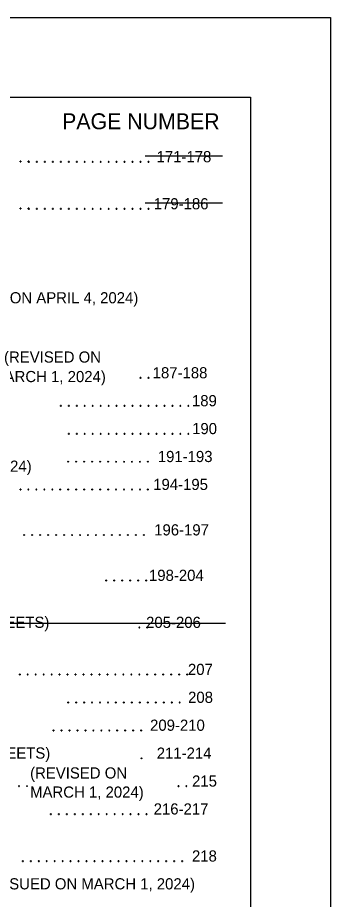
# Model space of a CAD drawing. Extents: x 0 to 1.42, y 0 to 0.92.
# Drawn here: x 1.2532 to 1.4167, y 0.4557 to 0.9167 of the extents above; entities that cross this region are included whole.
import ezdxf

# ---------------------------------------------------------------- set-up
doc = ezdxf.new("R2010")
doc.units = 0
for name, color, linetype in [('DRAFT_Text-Notes', 7, 'Continuous'), ('DRAFT_Text-Titles', 7, 'Continuous'), ('SHEET_Lines', 7, 'Continuous'), ('SHEET_Plot Boundary', 7, 'Continuous')]:
    doc.layers.add(name, color=color, linetype=linetype)

msp = doc.modelspace()

# ---------------------------------------------------------------- linework, layer by layer
at = {"layer": 'DRAFT_Text-Notes'}
for centre in [(1.2547, 0.84146), (1.25887, 0.84146), (1.25908, 0.84125), (1.26324, 0.84125), (1.26741, 0.84125), (1.27158, 0.84125), (1.27574, 0.84125), (1.27991, 0.84125), (1.28408, 0.84125), (1.28824, 0.84125), (1.29241, 0.84125), (1.29658, 0.84125), (1.30074, 0.84125), (1.30491, 0.84125), (1.30908, 0.84125), (1.31324, 0.84125), (1.31741, 0.84125), (1.32158, 0.84125), (1.2547, 0.81687), (1.25887, 0.81687), (1.25908, 0.81666), (1.26324, 0.81666), (1.26741, 0.81666), (1.27158, 0.81666), (1.27574, 0.81666), (1.27991, 0.81666), (1.28408, 0.81666), (1.28824, 0.81666), (1.29241, 0.81666), (1.29658, 0.81666), (1.30074, 0.81666), (1.30491, 0.81666), (1.30908, 0.81666), (1.31324, 0.81666), (1.31741, 0.81666), (1.32158, 0.81666), (1.31741, 0.72829), (1.32158, 0.72829), (1.27574, 0.7137), (1.27991, 0.7137), (1.28408, 0.7137), (1.28824, 0.7137), (1.29241, 0.7137), (1.29658, 0.7137), (1.30074, 0.7137), (1.30491, 0.7137), (1.30908, 0.7137), (1.31324, 0.7137), (1.31741, 0.7137), (1.32158, 0.7137), (1.32574, 0.7137), (1.32991, 0.7137), (1.33408, 0.7137), (1.33824, 0.7137), (1.34241, 0.7137), (1.27991, 0.6991), (1.28408, 0.6991), (1.28824, 0.6991), (1.29241, 0.6991), (1.29658, 0.6991), (1.30074, 0.6991), (1.30491, 0.6991), (1.30908, 0.6991), (1.31324, 0.6991), (1.31741, 0.6991), (1.32158, 0.6991), (1.32574, 0.6991), (1.32991, 0.6991), (1.33408, 0.6991), (1.33824, 0.6991), (1.34241, 0.6991), (1.27962, 0.68451), (1.28379, 0.68451), (1.28795, 0.68451), (1.29212, 0.68451), (1.29629, 0.68451), (1.30045, 0.68451), (1.30462, 0.68451), (1.30879, 0.68451), (1.31295, 0.68451), (1.31712, 0.68451), (1.32129, 0.68451), (1.25462, 0.66992), (1.25879, 0.66992), (1.26295, 0.66992), (1.26712, 0.66992), (1.27129, 0.66992), (1.27545, 0.66992), (1.27962, 0.66992), (1.28379, 0.66992), (1.28795, 0.66992), (1.29212, 0.66992), (1.29629, 0.66992), (1.30045, 0.66992), (1.30462, 0.66992), (1.30879, 0.66992), (1.31295, 0.66992), (1.31712, 0.66992), (1.32129, 0.66992), (1.25662, 0.64616), (1.26079, 0.64616), (1.26495, 0.64616), (1.26912, 0.64616), (1.27329, 0.64616), (1.27745, 0.64616), (1.28162, 0.64616), (1.28579, 0.64616), (1.28995, 0.64616), (1.29412, 0.64616), (1.29829, 0.64616), (1.30245, 0.64616), (1.30662, 0.64616), (1.31079, 0.64616), (1.31495, 0.64616), (1.31912, 0.64616), (1.2995, 0.62239), (1.30367, 0.62239), (1.30784, 0.62239), (1.312, 0.62239), (1.31617, 0.62239), (1.32034, 0.62239), (1.31677, 0.5978), (1.32094, 0.5978), (1.25427, 0.57321), (1.25844, 0.57321), (1.2626, 0.57321), (1.26677, 0.57321), (1.27094, 0.57321), (1.2751, 0.57321), (1.27927, 0.57321), (1.28344, 0.57321), (1.2876, 0.57321), (1.29177, 0.57321), (1.29594, 0.57321), (1.3001, 0.57321), (1.30427, 0.57321), (1.30844, 0.57321), (1.3126, 0.57321), (1.31677, 0.57321), (1.32094, 0.57321), (1.3251, 0.57321), (1.32927, 0.57321), (1.33344, 0.57321), (1.3376, 0.57321), (1.34177, 0.57321), (1.27956, 0.55862), (1.28373, 0.55862), (1.2879, 0.55862), (1.29206, 0.55862), (1.29623, 0.55862), (1.3004, 0.55862), (1.30456, 0.55862), (1.30873, 0.55862), (1.3129, 0.55862), (1.31706, 0.55862), (1.32123, 0.55862), (1.3254, 0.55862), (1.32956, 0.55862), (1.33373, 0.55862), (1.3379, 0.55862), (1.27193, 0.54402), (1.2761, 0.54402), (1.28026, 0.54402), (1.28443, 0.54402), (1.2886, 0.54402), (1.29276, 0.54402), (1.29693, 0.54402), (1.3011, 0.54402), (1.30526, 0.54402), (1.30943, 0.54402), (1.3136, 0.54402), (1.31776, 0.54402), (1.31797, 0.52943), (1.25389, 0.51484), (1.25806, 0.51484), (1.33723, 0.51484), (1.34139, 0.51484), (1.27056, 0.50025), (1.27473, 0.50025), (1.27889, 0.50025), (1.28306, 0.50025), (1.28723, 0.50025), (1.29139, 0.50025), (1.29556, 0.50025), (1.29973, 0.50025), (1.30389, 0.50025), (1.30806, 0.50025), (1.31223, 0.50025), (1.31639, 0.50025), (1.32056, 0.50025), (1.25586, 0.47566), (1.26003, 0.47566), (1.2642, 0.47566), (1.26836, 0.47566), (1.27253, 0.47566), (1.2767, 0.47566), (1.28086, 0.47566), (1.28503, 0.47566), (1.2892, 0.47566), (1.29336, 0.47566), (1.29753, 0.47566), (1.3017, 0.47566), (1.30586, 0.47566), (1.31003, 0.47566), (1.3142, 0.47566), (1.31836, 0.47566), (1.32253, 0.47566), (1.3267, 0.47566), (1.33086, 0.47566), (1.33503, 0.47566), (1.3392, 0.47566)]:
    msp.add_circle(centre, 0.000208, dxfattribs=at)
for centre, start, end in [((1.2547, 0.84146), 0, 180), ((1.2547, 0.84146), 180, 0), ((1.25887, 0.84146), 0, 180), ((1.25887, 0.84146), 180, 0), ((1.25908, 0.84125), 0, 180), ((1.25908, 0.84125), 180, 0), ((1.26324, 0.84125), 0, 180), ((1.26324, 0.84125), 180, 0), ((1.26741, 0.84125), 0, 180), ((1.26741, 0.84125), 180, 0), ((1.27158, 0.84125), 0, 180), ((1.27158, 0.84125), 180, 0), ((1.27574, 0.84125), 0, 180), ((1.27574, 0.84125), 180, 0), ((1.27991, 0.84125), 0, 180), ((1.27991, 0.84125), 180, 0), ((1.28408, 0.84125), 0, 180), ((1.28408, 0.84125), 180, 0), ((1.28824, 0.84125), 0, 180), ((1.28824, 0.84125), 180, 0), ((1.29241, 0.84125), 0, 180), ((1.29241, 0.84125), 180, 0), ((1.29658, 0.84125), 0, 180), ((1.29658, 0.84125), 180, 0), ((1.30074, 0.84125), 0, 180), ((1.30074, 0.84125), 180, 0), ((1.30491, 0.84125), 0, 180), ((1.30491, 0.84125), 180, 0), ((1.30908, 0.84125), 0, 180), ((1.30908, 0.84125), 180, 0), ((1.31324, 0.84125), 0, 180), ((1.31324, 0.84125), 180, 0), ((1.31741, 0.84125), 0, 180), ((1.31741, 0.84125), 180, 0), ((1.32158, 0.84125), 0, 180), ((1.32158, 0.84125), 180, 0), ((1.2547, 0.81687), 0, 180), ((1.2547, 0.81687), 180, 0), ((1.25887, 0.81687), 0, 180), ((1.25887, 0.81687), 180, 0), ((1.25908, 0.81666), 0, 180), ((1.25908, 0.81666), 180, 0), ((1.26324, 0.81666), 0, 180), ((1.26324, 0.81666), 180, 0), ((1.26741, 0.81666), 0, 180), ((1.26741, 0.81666), 180, 0), ((1.27158, 0.81666), 0, 180), ((1.27158, 0.81666), 180, 0), ((1.27574, 0.81666), 0, 180), ((1.27574, 0.81666), 180, 0), ((1.27991, 0.81666), 0, 180), ((1.27991, 0.81666), 180, 0), ((1.28408, 0.81666), 0, 180), ((1.28408, 0.81666), 180, 0), ((1.28824, 0.81666), 0, 180), ((1.28824, 0.81666), 180, 0), ((1.29241, 0.81666), 0, 180), ((1.29241, 0.81666), 180, 0), ((1.29658, 0.81666), 0, 180), ((1.29658, 0.81666), 180, 0), ((1.30074, 0.81666), 0, 180), ((1.30074, 0.81666), 180, 0), ((1.30491, 0.81666), 0, 180), ((1.30491, 0.81666), 180, 0), ((1.30908, 0.81666), 0, 180), ((1.30908, 0.81666), 180, 0), ((1.31324, 0.81666), 0, 180), ((1.31324, 0.81666), 180, 0), ((1.31741, 0.81666), 0, 180), ((1.31741, 0.81666), 180, 0), ((1.32158, 0.81666), 0, 180), ((1.32158, 0.81666), 180, 0), ((1.31741, 0.72829), 0, 180), ((1.32158, 0.72829), 0, 180), ((1.31741, 0.72829), 180, 0), ((1.32158, 0.72829), 180, 0), ((1.27574, 0.7137), 0, 180), ((1.27574, 0.7137), 180, 0), ((1.27991, 0.7137), 0, 180), ((1.27991, 0.7137), 180, 0), ((1.28408, 0.7137), 0, 180), ((1.28408, 0.7137), 180, 0), ((1.28824, 0.7137), 0, 180), ((1.28824, 0.7137), 180, 0), ((1.29241, 0.7137), 0, 180), ((1.29241, 0.7137), 180, 0), ((1.29658, 0.7137), 0, 180), ((1.29658, 0.7137), 180, 0), ((1.30074, 0.7137), 0, 180), ((1.30074, 0.7137), 180, 0), ((1.30491, 0.7137), 0, 180), ((1.30491, 0.7137), 180, 0), ((1.30908, 0.7137), 0, 180), ((1.30908, 0.7137), 180, 0), ((1.31324, 0.7137), 0, 180), ((1.31324, 0.7137), 180, 0), ((1.31741, 0.7137), 0, 180), ((1.31741, 0.7137), 180, 0), ((1.32158, 0.7137), 0, 180), ((1.32158, 0.7137), 180, 0), ((1.32574, 0.7137), 0, 180), ((1.32574, 0.7137), 180, 0), ((1.32991, 0.7137), 0, 180), ((1.32991, 0.7137), 180, 0), ((1.33408, 0.7137), 0, 180), ((1.33408, 0.7137), 180, 0), ((1.33824, 0.7137), 0, 180), ((1.33824, 0.7137), 180, 0), ((1.34241, 0.7137), 0, 180), ((1.34241, 0.7137), 180, 0), ((1.27991, 0.6991), 0, 180), ((1.27991, 0.6991), 180, 0), ((1.28408, 0.6991), 0, 180), ((1.28408, 0.6991), 180, 0), ((1.28824, 0.6991), 0, 180), ((1.28824, 0.6991), 180, 0), ((1.29241, 0.6991), 0, 180), ((1.29241, 0.6991), 180, 0), ((1.29658, 0.6991), 0, 180), ((1.29658, 0.6991), 180, 0), ((1.30074, 0.6991), 0, 180), ((1.30074, 0.6991), 180, 0), ((1.30491, 0.6991), 0, 180), ((1.30491, 0.6991), 180, 0), ((1.30908, 0.6991), 0, 180), ((1.30908, 0.6991), 180, 0), ((1.31324, 0.6991), 0, 180), ((1.31324, 0.6991), 180, 0), ((1.31741, 0.6991), 0, 180), ((1.31741, 0.6991), 180, 0), ((1.32158, 0.6991), 0, 180), ((1.32158, 0.6991), 180, 0), ((1.32574, 0.6991), 0, 180), ((1.32574, 0.6991), 180, 0), ((1.32991, 0.6991), 0, 180), ((1.32991, 0.6991), 180, 0), ((1.33408, 0.6991), 0, 180), ((1.33408, 0.6991), 180, 0), ((1.33824, 0.6991), 0, 180), ((1.33824, 0.6991), 180, 0), ((1.34241, 0.6991), 0, 180), ((1.34241, 0.6991), 180, 0), ((1.27962, 0.68451), 0, 180), ((1.27962, 0.68451), 180, 0), ((1.28379, 0.68451), 0, 180), ((1.28379, 0.68451), 180, 0), ((1.28795, 0.68451), 0, 180), ((1.28795, 0.68451), 180, 0), ((1.29212, 0.68451), 0, 180), ((1.29212, 0.68451), 180, 0), ((1.29629, 0.68451), 0, 180), ((1.29629, 0.68451), 180, 0), ((1.30045, 0.68451), 0, 180), ((1.30045, 0.68451), 180, 0), ((1.30462, 0.68451), 0, 180), ((1.30462, 0.68451), 180, 0), ((1.30879, 0.68451), 0, 180), ((1.30879, 0.68451), 180, 0), ((1.31295, 0.68451), 0, 180), ((1.31295, 0.68451), 180, 0), ((1.31712, 0.68451), 0, 180), ((1.31712, 0.68451), 180, 0), ((1.32129, 0.68451), 0, 180), ((1.32129, 0.68451), 180, 0), ((1.25462, 0.66992), 0, 180), ((1.25462, 0.66992), 180, 0), ((1.25879, 0.66992), 0, 180), ((1.25879, 0.66992), 180, 0), ((1.26295, 0.66992), 0, 180), ((1.26295, 0.66992), 180, 0), ((1.26712, 0.66992), 0, 180), ((1.26712, 0.66992), 180, 0), ((1.27129, 0.66992), 0, 180), ((1.27129, 0.66992), 180, 0), ((1.27545, 0.66992), 0, 180), ((1.27545, 0.66992), 180, 0), ((1.27962, 0.66992), 0, 180), ((1.27962, 0.66992), 180, 0), ((1.28379, 0.66992), 0, 180), ((1.28379, 0.66992), 180, 0), ((1.28795, 0.66992), 0, 180), ((1.28795, 0.66992), 180, 0), ((1.29212, 0.66992), 0, 180), ((1.29212, 0.66992), 180, 0), ((1.29629, 0.66992), 0, 180), ((1.29629, 0.66992), 180, 0), ((1.30045, 0.66992), 0, 180), ((1.30045, 0.66992), 180, 0), ((1.30462, 0.66992), 0, 180), ((1.30462, 0.66992), 180, 0), ((1.30879, 0.66992), 0, 180), ((1.30879, 0.66992), 180, 0), ((1.31295, 0.66992), 0, 180), ((1.31295, 0.66992), 180, 0), ((1.31712, 0.66992), 0, 180), ((1.31712, 0.66992), 180, 0), ((1.32129, 0.66992), 0, 180), ((1.32129, 0.66992), 180, 0), ((1.25662, 0.64616), 0, 180), ((1.25662, 0.64616), 180, 0), ((1.26079, 0.64616), 0, 180), ((1.26079, 0.64616), 180, 0), ((1.26495, 0.64616), 0, 180), ((1.26495, 0.64616), 180, 0), ((1.26912, 0.64616), 0, 180), ((1.26912, 0.64616), 180, 0), ((1.27329, 0.64616), 0, 180), ((1.27329, 0.64616), 180, 0), ((1.27745, 0.64616), 0, 180), ((1.27745, 0.64616), 180, 0), ((1.28162, 0.64616), 0, 180), ((1.28162, 0.64616), 180, 0), ((1.28579, 0.64616), 0, 180), ((1.28579, 0.64616), 180, 0), ((1.28995, 0.64616), 0, 180), ((1.28995, 0.64616), 180, 0), ((1.29412, 0.64616), 0, 180), ((1.29412, 0.64616), 180, 0), ((1.29829, 0.64616), 0, 180), ((1.29829, 0.64616), 180, 0), ((1.30245, 0.64616), 0, 180), ((1.30245, 0.64616), 180, 0), ((1.30662, 0.64616), 0, 180), ((1.30662, 0.64616), 180, 0), ((1.31079, 0.64616), 0, 180), ((1.31079, 0.64616), 180, 0), ((1.31495, 0.64616), 0, 180), ((1.31495, 0.64616), 180, 0), ((1.31912, 0.64616), 0, 180), ((1.31912, 0.64616), 180, 0), ((1.2995, 0.62239), 0, 180), ((1.2995, 0.62239), 180, 0), ((1.30367, 0.62239), 0, 180), ((1.30367, 0.62239), 180, 0), ((1.30784, 0.62239), 0, 180), ((1.30784, 0.62239), 180, 0), ((1.312, 0.62239), 0, 180), ((1.312, 0.62239), 180, 0), ((1.31617, 0.62239), 0, 180), ((1.31617, 0.62239), 180, 0), ((1.32034, 0.62239), 0, 180), ((1.32034, 0.62239), 180, 0), ((1.31677, 0.5978), 0, 180), ((1.31677, 0.5978), 180, 0), ((1.32094, 0.5978), 0, 180), ((1.32094, 0.5978), 180, 0), ((1.25427, 0.57321), 0, 180), ((1.25427, 0.57321), 180, 0), ((1.25844, 0.57321), 0, 180), ((1.25844, 0.57321), 180, 0), ((1.2626, 0.57321), 0, 180), ((1.2626, 0.57321), 180, 0), ((1.26677, 0.57321), 0, 180), ((1.26677, 0.57321), 180, 0), ((1.27094, 0.57321), 0, 180), ((1.27094, 0.57321), 180, 0), ((1.2751, 0.57321), 0, 180), ((1.2751, 0.57321), 180, 0), ((1.27927, 0.57321), 0, 180), ((1.27927, 0.57321), 180, 0), ((1.28344, 0.57321), 0, 180), ((1.28344, 0.57321), 180, 0), ((1.2876, 0.57321), 0, 180), ((1.2876, 0.57321), 180, 0), ((1.29177, 0.57321), 0, 180), ((1.29177, 0.57321), 180, 0), ((1.29594, 0.57321), 0, 180), ((1.29594, 0.57321), 180, 0), ((1.3001, 0.57321), 0, 180), ((1.3001, 0.57321), 180, 0), ((1.30427, 0.57321), 0, 180), ((1.30427, 0.57321), 180, 0), ((1.30844, 0.57321), 0, 180), ((1.30844, 0.57321), 180, 0), ((1.3126, 0.57321), 0, 180), ((1.3126, 0.57321), 180, 0), ((1.31677, 0.57321), 0, 180), ((1.31677, 0.57321), 180, 0), ((1.32094, 0.57321), 0, 180), ((1.32094, 0.57321), 180, 0), ((1.3251, 0.57321), 0, 180), ((1.3251, 0.57321), 180, 0), ((1.32927, 0.57321), 0, 180), ((1.32927, 0.57321), 180, 0), ((1.33344, 0.57321), 0, 180), ((1.33344, 0.57321), 180, 0), ((1.3376, 0.57321), 0, 180), ((1.3376, 0.57321), 180, 0), ((1.34177, 0.57321), 0, 180), ((1.34177, 0.57321), 180, 0), ((1.27956, 0.55862), 0, 180), ((1.27956, 0.55862), 180, 0), ((1.28373, 0.55862), 0, 180), ((1.28373, 0.55862), 180, 0), ((1.2879, 0.55862), 0, 180), ((1.2879, 0.55862), 180, 0), ((1.29206, 0.55862), 0, 180), ((1.29206, 0.55862), 180, 0), ((1.29623, 0.55862), 0, 180), ((1.29623, 0.55862), 180, 0), ((1.3004, 0.55862), 0, 180), ((1.3004, 0.55862), 180, 0), ((1.30456, 0.55862), 0, 180), ((1.30456, 0.55862), 180, 0), ((1.30873, 0.55862), 0, 180), ((1.30873, 0.55862), 180, 0), ((1.3129, 0.55862), 0, 180), ((1.3129, 0.55862), 180, 0), ((1.31706, 0.55862), 0, 180), ((1.31706, 0.55862), 180, 0), ((1.32123, 0.55862), 0, 180), ((1.32123, 0.55862), 180, 0), ((1.3254, 0.55862), 0, 180), ((1.3254, 0.55862), 180, 0), ((1.32956, 0.55862), 0, 180), ((1.32956, 0.55862), 180, 0), ((1.33373, 0.55862), 0, 180), ((1.33373, 0.55862), 180, 0), ((1.3379, 0.55862), 0, 180), ((1.3379, 0.55862), 180, 0), ((1.27193, 0.54402), 0, 180), ((1.27193, 0.54402), 180, 0), ((1.2761, 0.54402), 0, 180), ((1.2761, 0.54402), 180, 0), ((1.28026, 0.54402), 0, 180), ((1.28026, 0.54402), 180, 0), ((1.28443, 0.54402), 0, 180), ((1.28443, 0.54402), 180, 0), ((1.2886, 0.54402), 0, 180), ((1.2886, 0.54402), 180, 0), ((1.29276, 0.54402), 0, 180), ((1.29276, 0.54402), 180, 0), ((1.29693, 0.54402), 0, 180), ((1.29693, 0.54402), 180, 0), ((1.3011, 0.54402), 0, 180), ((1.3011, 0.54402), 180, 0), ((1.30526, 0.54402), 0, 180), ((1.30526, 0.54402), 180, 0), ((1.30943, 0.54402), 0, 180), ((1.30943, 0.54402), 180, 0), ((1.3136, 0.54402), 0, 180), ((1.3136, 0.54402), 180, 0), ((1.31776, 0.54402), 0, 180), ((1.31776, 0.54402), 180, 0), ((1.31797, 0.52943), 0, 180), ((1.31797, 0.52943), 180, 0), ((1.25389, 0.51484), 0, 180), ((1.25389, 0.51484), 180, 0), ((1.33723, 0.51484), 0, 180), ((1.33723, 0.51484), 180, 0), ((1.34139, 0.51484), 0, 180), ((1.34139, 0.51484), 180, 0), ((1.27056, 0.50025), 0, 180), ((1.27056, 0.50025), 180, 0), ((1.27473, 0.50025), 0, 180), ((1.27473, 0.50025), 180, 0), ((1.27889, 0.50025), 0, 180), ((1.27889, 0.50025), 180, 0), ((1.28306, 0.50025), 0, 180), ((1.28306, 0.50025), 180, 0), ((1.28723, 0.50025), 0, 180), ((1.28723, 0.50025), 180, 0), ((1.29139, 0.50025), 0, 180), ((1.29139, 0.50025), 180, 0), ((1.29556, 0.50025), 0, 180), ((1.29556, 0.50025), 180, 0), ((1.29973, 0.50025), 0, 180), ((1.29973, 0.50025), 180, 0), ((1.30389, 0.50025), 0, 180), ((1.30389, 0.50025), 180, 0), ((1.30806, 0.50025), 0, 180), ((1.30806, 0.50025), 180, 0), ((1.31223, 0.50025), 0, 180), ((1.31223, 0.50025), 180, 0), ((1.31639, 0.50025), 0, 180), ((1.31639, 0.50025), 180, 0), ((1.32056, 0.50025), 0, 180), ((1.32056, 0.50025), 180, 0), ((1.25586, 0.47566), 0, 180), ((1.25586, 0.47566), 180, 0), ((1.26003, 0.47566), 0, 180), ((1.26003, 0.47566), 180, 0), ((1.2642, 0.47566), 0, 180), ((1.2642, 0.47566), 180, 0), ((1.26836, 0.47566), 0, 180), ((1.26836, 0.47566), 180, 0), ((1.27253, 0.47566), 0, 180), ((1.27253, 0.47566), 180, 0), ((1.2767, 0.47566), 0, 180), ((1.2767, 0.47566), 180, 0), ((1.28086, 0.47566), 0, 180), ((1.28086, 0.47566), 180, 0), ((1.28503, 0.47566), 0, 180), ((1.28503, 0.47566), 180, 0), ((1.2892, 0.47566), 0, 180), ((1.2892, 0.47566), 180, 0), ((1.29336, 0.47566), 0, 180), ((1.29336, 0.47566), 180, 0), ((1.29753, 0.47566), 0, 180), ((1.29753, 0.47566), 180, 0), ((1.3017, 0.47566), 0, 180), ((1.3017, 0.47566), 180, 0), ((1.30586, 0.47566), 0, 180), ((1.30586, 0.47566), 180, 0), ((1.31003, 0.47566), 0, 180), ((1.31003, 0.47566), 180, 0), ((1.3142, 0.47566), 0, 180), ((1.3142, 0.47566), 180, 0), ((1.31836, 0.47566), 0, 180), ((1.31836, 0.47566), 180, 0), ((1.32253, 0.47566), 0, 180), ((1.32253, 0.47566), 180, 0), ((1.3267, 0.47566), 0, 180), ((1.3267, 0.47566), 180, 0), ((1.33086, 0.47566), 0, 180), ((1.33086, 0.47566), 180, 0), ((1.33503, 0.47566), 0, 180), ((1.33503, 0.47566), 180, 0), ((1.3392, 0.47566), 0, 180), ((1.3392, 0.47566), 180, 0)]:
    msp.add_arc(centre, 0.000208, start, end, dxfattribs=at)
at = {"layer": 'DRAFT_Text-Titles'}
for p, q in [((1.31989, 0.84436), (1.36032, 0.84436)), ((1.31989, 0.81977), (1.36032, 0.81977)), ((0.96512, 0.60007), (1.36191, 0.60007))]:
    msp.add_line(p, q, dxfattribs=at)
at = {"layer": 'SHEET_Lines'}
msp.add_lwpolyline([(0.08333, 0.875), (1.375, 0.875), (1.375, 0.125), (0.08333, 0.125)], close=True, dxfattribs=at)
at = {"layer": 'SHEET_Plot Boundary'}
msp.add_lwpolyline([(0, 0.91667), (1.41667, 0.91667), (1.41667, 0), (0, 0)], close=True, dxfattribs=at)

# ---------------------------------------------------------------- texts
at = {"layer": 'DRAFT_Text-Notes'}
for s, height, p in [('171-178', 0.005833, (1.3258, 0.84104)), ('179-186', 0.005833, (1.32433, 0.81645)), ('187-188', 0.005833, (1.32377, 0.72808)), ('189', 0.005833, (1.3443, 0.71349)), ('190', 0.005833, (1.34439, 0.6989)), ('191-193', 0.005833, (1.32644, 0.6843)), ('194-195', 0.005833, (1.32405, 0.66971)), ('196-197', 0.005833, (1.32456, 0.64595)), ('198-204', 0.005833, (1.32184, 0.62218)), ('PEDESTRIAN PUSH BUTTON POST ASSEMBLY (2 SHEETS)', 0.0058333, (1.04917, 0.59763)), ('205-206', 0.005833, (1.32034, 0.59759)), ('207', 0.005833, (1.3422, 0.573)), ('208', 0.005833, (1.34229, 0.55841)), ('209-210', 0.005833, (1.32241, 0.54382)), ('FLASHING BEACON AND SIGN INSTALLATIONS (4 SHEETS)', 0.0058333, (1.0483, 0.52926)), ('211-214', 0.005833, (1.3259, 0.52922)), ('215', 0.005833, (1.34436, 0.51463)), ('216-217', 0.005833, (1.32429, 0.50004)), ('218', 0.005833, (1.34431, 0.47545))]:
    msp.add_text(s, height=height, dxfattribs=at).set_placement(p)
at = {"layer": 'DRAFT_Text-Titles'}
for s, height, p in [('PAGE NUMBER', 0.0083333, (1.27642, 0.85831)), ('(NEW, ISSUED ON APRIL 4, 2024)', 0.0058333, (1.19271, 0.7673)), ('(REVISED ON', 0.0058333, (1.24606, 0.73631)), ('MARCH 1, 2024)', 0.0058333, (1.23988, 0.7261)), ('MARCH 1, 2024)', 0.0058333, (1.2011, 0.67925)), ('(REVISED ON', 0.0058333, (1.25969, 0.51886)), ('MARCH 1, 2024)', 0.0058333, (1.25969, 0.50886)), ('(NEW, ISSUED ON MARCH 1, 2024)', 0.0058333, (1.21628, 0.46089))]:
    msp.add_text(s, height=height, dxfattribs=at).set_placement(p)

doc.saveas('drawing.dxf')
